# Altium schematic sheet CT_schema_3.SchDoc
size 578 x 363 mm
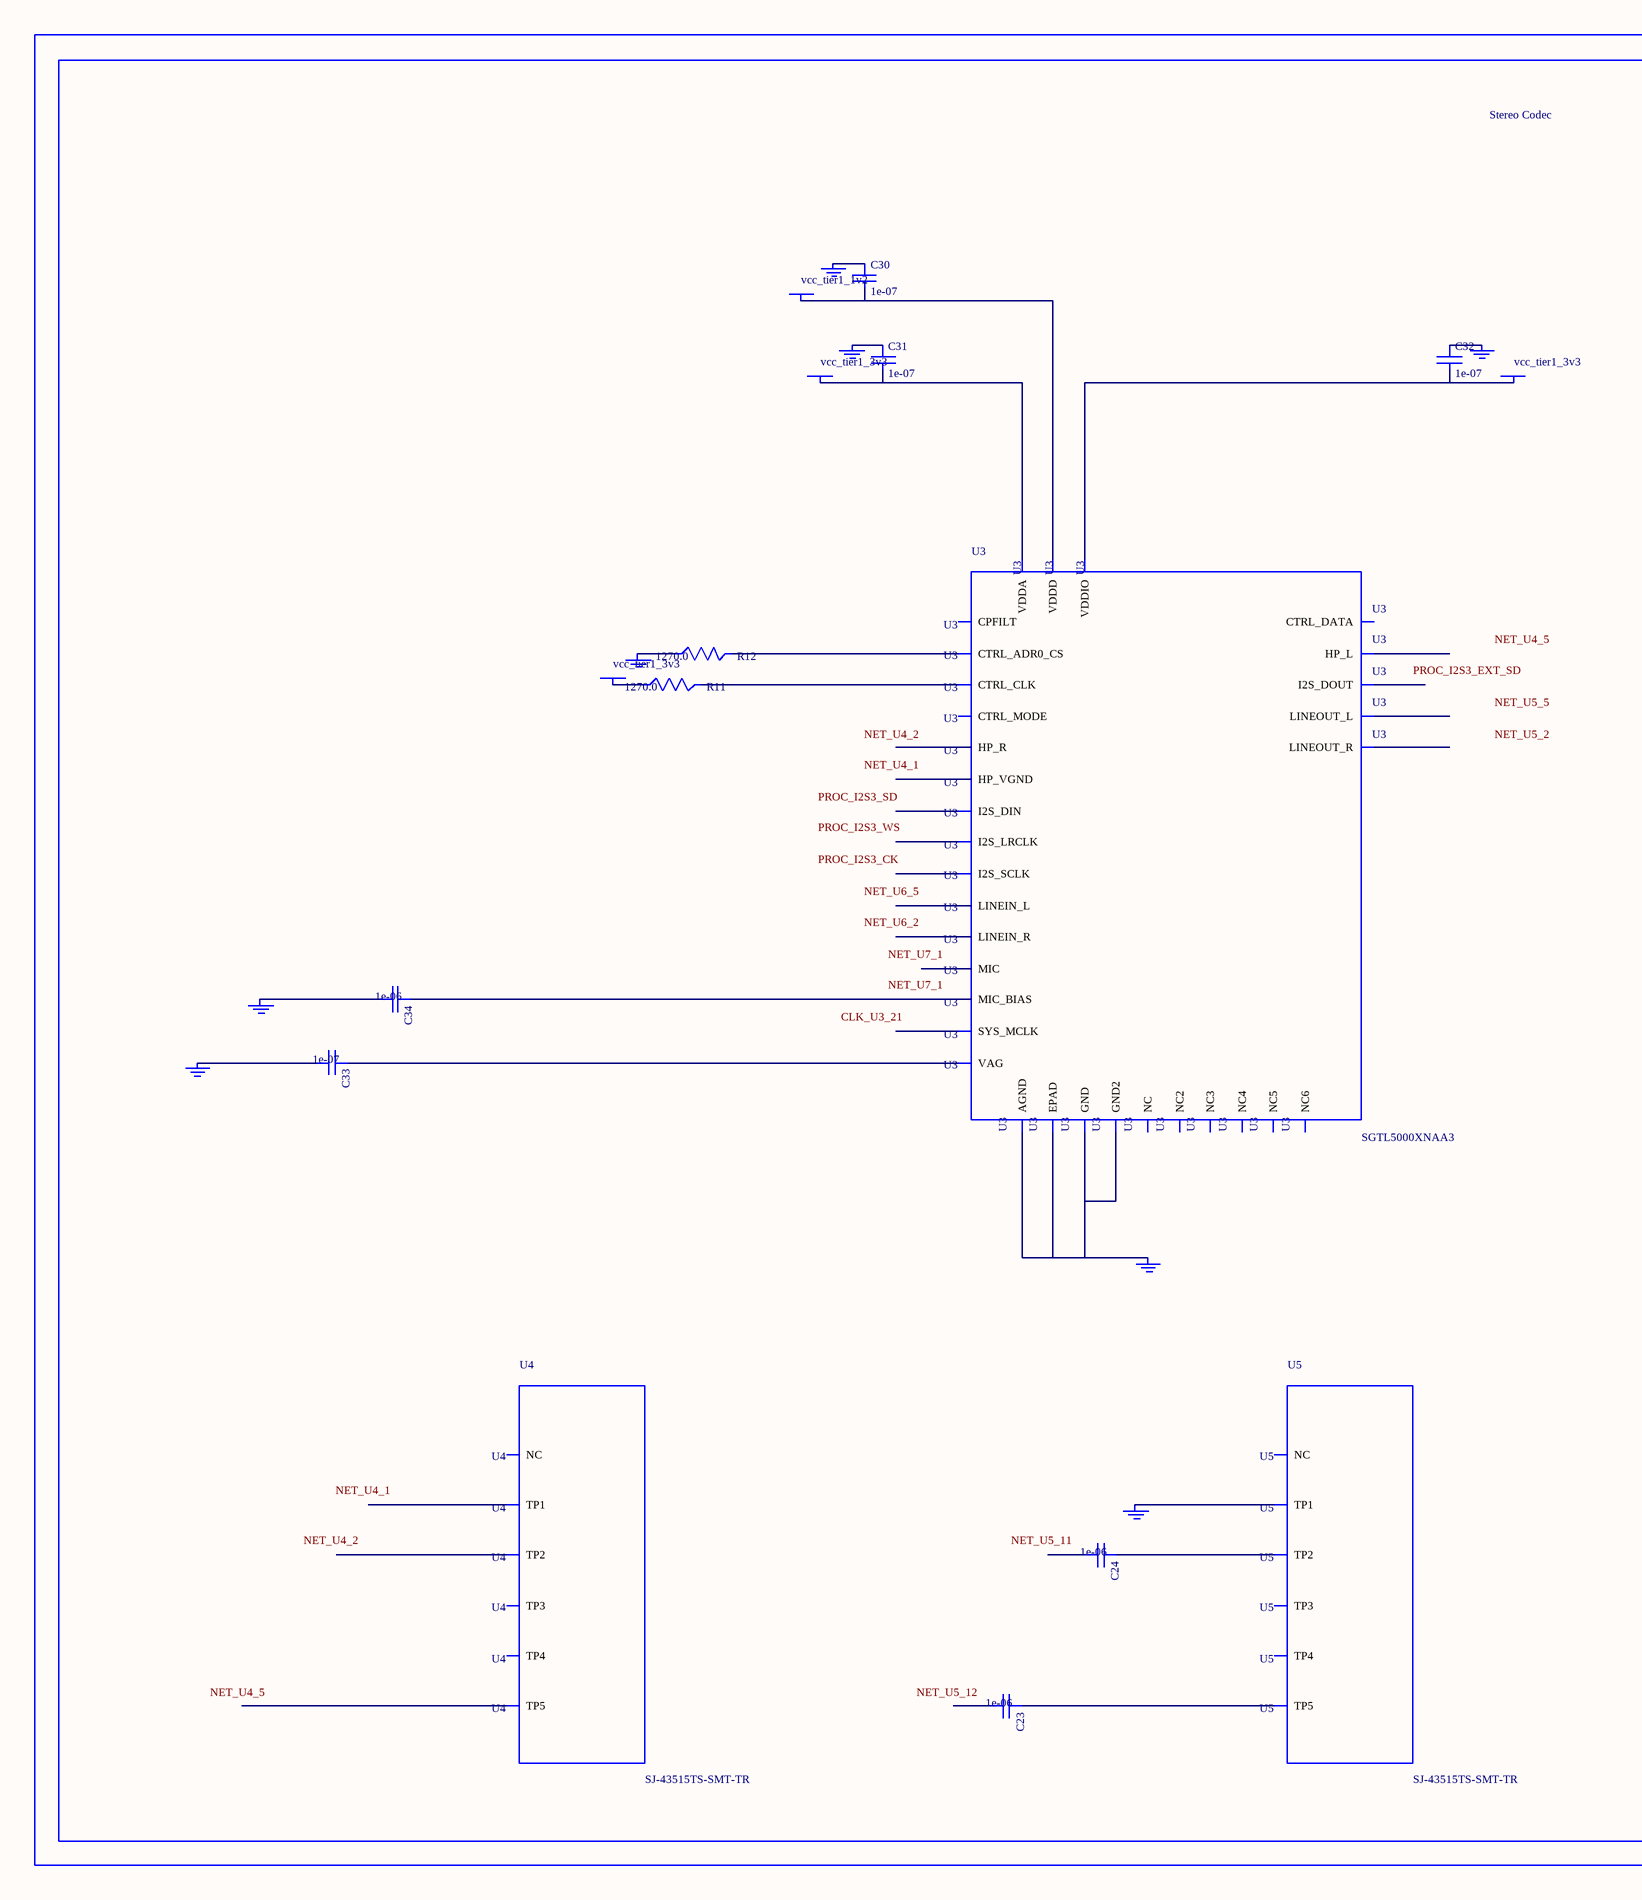
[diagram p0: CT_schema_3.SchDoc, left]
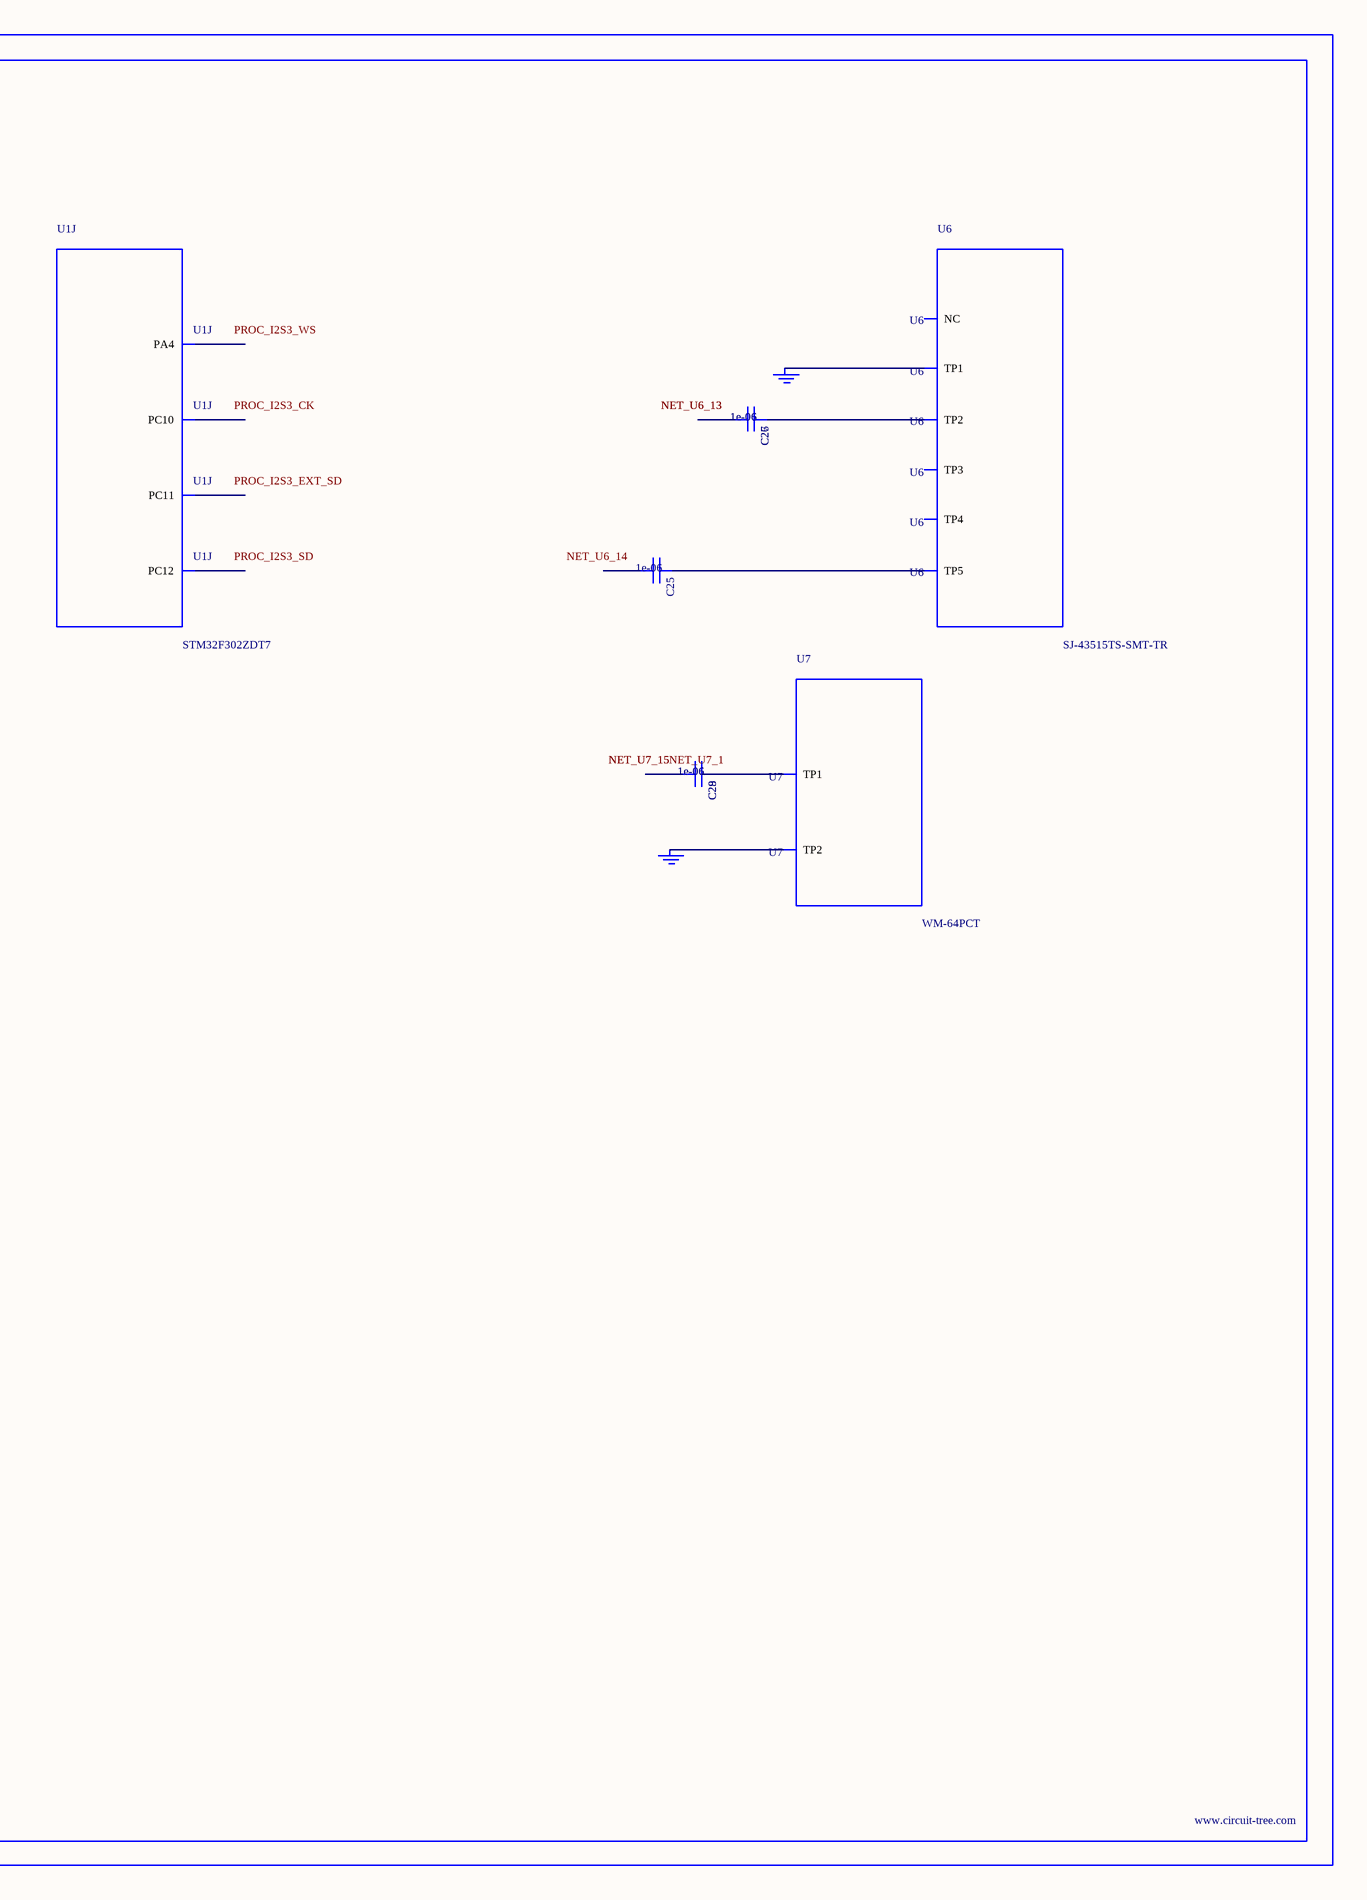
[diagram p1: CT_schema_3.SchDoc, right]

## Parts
BORDER2  (no value)
C23  1e-06  [C0603]
C24  1e-06  [C0603]
C25  1e-06  [C0603]
C26  1e-06  [C0603]
C27  1e-06  [C0603]
C28  1e-06  [C0603]
C29  1e-06  [C0603]
C30  1e-07  [C0402]
C31  1e-07  [C0402]
C32  1e-07  [C0402]
C33  1e-07  [C0402]
C34  1e-06  [C0603]
GND_INSTANCE_2_0  (no value)
GND_INSTANCE_2_1  (no value)
GND_INSTANCE_2_2  (no value)
GND_INSTANCE_2_3  (no value)
GND_INSTANCE_2_4  (no value)
GND_INSTANCE_2_5  (no value)
GND_INSTANCE_2_6  (no value)
GND_INSTANCE_2_7  (no value)
GND_INSTANCE_2_8  (no value)
GND_INSTANCE_2_9  (no value)
GND_INSTANCE_2_10  (no value)
POWER_INSTANCE_2_0  vcc_tier1_3v3
POWER_INSTANCE_2_1  vcc_tier1_3v3
POWER_INSTANCE_2_2  vcc_tier1_3v3
POWER_INSTANCE_2_3  vcc_tier1_1v2
R11  1270.0  [R0603]
R12  1270.0  [R0603]
U1  STM32F302ZDT7  [LQFP144]  (part J of 12)
U3  SGTL5000XNAA3  [QFN-32]
U4  SJ-43515TS-SMT-TR  [SJ-43515TS-SMT-TR]
U5  SJ-43515TS-SMT-TR  [SJ-43515TS-SMT-TR]
U6  SJ-43515TS-SMT-TR  [SJ-43515TS-SMT-TR]
U7  WM-64PCT  [WM-64PC]

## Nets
NetC23_1: C23.1 U5.5(TP5)
NetC24_1: C24.1 U5.2(TP2)
NetC25_1: C25.1 U6.5(TP5)
NetC26_1: C26.1 C27.1 U6.2(TP2)
NetC26_2: C26.2 C27.2
NetC28_1: C28.1 C29.1 U7.1(TP1)
NetC28_2: C28.2 C29.2
NetC30_1: C30.1 GND_INSTANCE_2_5.0(GND)
NetC30_2: C30.2 POWER_INSTANCE_2_3.0(PWR) U3.30(VDDD)
NetC31_1: C31.1 GND_INSTANCE_2_1.0(GND)
NetC31_2: C31.2 POWER_INSTANCE_2_0.0(PWR) U3.5(VDDA)
NetC32_1: C32.1 GND_INSTANCE_2_4.0(GND)
NetC32_2: C32.2 POWER_INSTANCE_2_1.0(PWR) U3.20(VDDIO)
NetC33_1: C33.1 U3.10(VAG)
NetC33_2: C33.2 GND_INSTANCE_2_2.0(GND)
NetC34_1: C34.1 U3.16(MIC_BIAS)
NetC34_2: C34.2 GND_INSTANCE_2_3.0(GND)
NetGND_INSTANCE_2_0_0: GND_INSTANCE_2_0.0(GND) U3.1(GND) U3.3(GND2) U3.7(AGND) U3.EXP(EPAD)
NetGND_INSTANCE_2_6_0: GND_INSTANCE_2_6.0(GND) R12.1
NetGND_INSTANCE_2_7_0: GND_INSTANCE_2_7.0(GND) U5.1(TP1)
NetGND_INSTANCE_2_8_0: GND_INSTANCE_2_8.0(GND) GND_INSTANCE_2_9.0(GND) U6.1(TP1)
NetGND_INSTANCE_2_10_0: GND_INSTANCE_2_10.0(GND) U7.2(TP2)
NetPOWER_INSTANCE_2_2_0: POWER_INSTANCE_2_2.0(PWR) R11.1
NetR11_2: R11.2 U3.29(CTRL_CLK)
NetR12_2: R12.2 U3.31(CTRL_ADR0_CS)

Not connected (* = marked no-connect by the designer): C23 2; C24 2; C25 2; U1 40(PA4) 111(PC10) 112(PC11) 113(PC12); U3 2(HP_R) 4(HP_VGND) 6(HP_L) 8(NC) 9(NC2) 11(LINEOUT_R) 12(LINEOUT_L) 13(LINEIN_R) 14(LINEIN_L) 15(MIC) 17(NC3) 18(CPFILT) 19(NC4) 21(SYS_MCLK) 22(NC5) 23(I2S_LRCLK) 24(I2S_SCLK) 25(I2S_DOUT) 26(I2S_DIN) 27(CTRL_DATA) 28(NC6) 32(CTRL_MODE); U4 1(TP1) 2(TP2) 3(TP3) 4(TP4) 5(TP5) 6(NC); U5 3(TP3) 4(TP4) 6(NC); U6 3(TP3) 4(TP4) 6(NC)

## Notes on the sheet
- Labels drawn without touching a wire or pin: CLK_U3_21, NET_U4_1, NET_U4_2, NET_U4_5, NET_U5_2, NET_U5_5, NET_U5_11, NET_U5_12, NET_U6_2, NET_U6_5, NET_U6_14, NET_U7_1, PROC_I2S3_CK, PROC_I2S3_EXT_SD, PROC_I2S3_SD, PROC_I2S3_WS

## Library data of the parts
BORDER2 = BORDER_PAGE2
C23-C29 C34 = C0603C105K3RACTU
C30-C33 = C0402C104K3RACTU
GND_INSTANCE_2_0-GND_INSTANCE_2_10 = GND
POWER_INSTANCE_2_0-POWER_INSTANCE_2_3 = PWR
R11 R12 = RC0603FR-071K27L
